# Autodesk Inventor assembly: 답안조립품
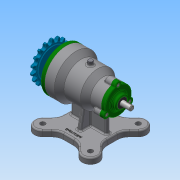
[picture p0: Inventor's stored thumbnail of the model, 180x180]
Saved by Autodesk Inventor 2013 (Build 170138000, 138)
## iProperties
Created: 2017-03
Part Number: 답안조립품
Document SubType Name: Assembly
Designer: Administrator
Author: Administrator
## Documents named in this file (14)
- C:\Users\Administrator\Desktop\470308V1014\답안조립품.iam
- C:\Users\Administrator\Desktop\470308V1014\본체.ipt
- C:\Users\Administrator\Desktop\470308V1014\뒤커버.ipt
- C:\Users\Administrator\Desktop\470308V1014\베어링-6200.ipt
- C:\Users\Administrator\Desktop\470308V1014\베어링-6203.ipt
- C:\Users\Administrator\Desktop\470308V1014\볼트 M4 x 12.ipt
- C:\Users\Administrator\Desktop\470308V1014\볼트 M5 x 10.ipt
- 볼트 M5 x 10.ipt
- C:\Users\Administrator\Desktop\470308V1014\스프로킷.ipt
- C:\Users\Administrator\Desktop\470308V1014\앞커버.ipt
- C:\Users\Administrator\Desktop\470308V1014\오일 실 10 20 7.ipt
- C:\Users\Administrator\Desktop\470308V1014\오일 실 17 30 8.ipt
- C:\Users\Administrator\Desktop\470308V1014\축.ipt
- C:\Users\Administrator\Desktop\470308V1014\키5x5.ipt
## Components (9 placed, 1 different names)
1. ISO 4762 M4 x 12:1
2. ISO 4762 M4 x 12:3
3. ISO 4762 M4 x 12:4
4. ISO 4762 M4 x 12:2
5. ISO 4762 M4 x 12:5
6. ISO 4762 M4 x 12:6
7. ISO 4762 M4 x 12:7
8. ISO 4762 M4 x 12:8
9. ISO 4762 M4 x 12:9
